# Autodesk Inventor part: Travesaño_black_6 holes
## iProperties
Created: 2008-01
Part Number: Travesaño_black_6 holes
Document SubType Name: Modeling
Designer: eruiz-tagle
Mass: 0.94817 g
Surface Area: 13.8587 cm^2
Volume: 0.94817 cm^3
Density: 1 g/cm^3
Author: eruiz-tagle
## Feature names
1. Extrusion1
2. Fillet1
3. Fillet2
4. Hole1
5. Mirror1
